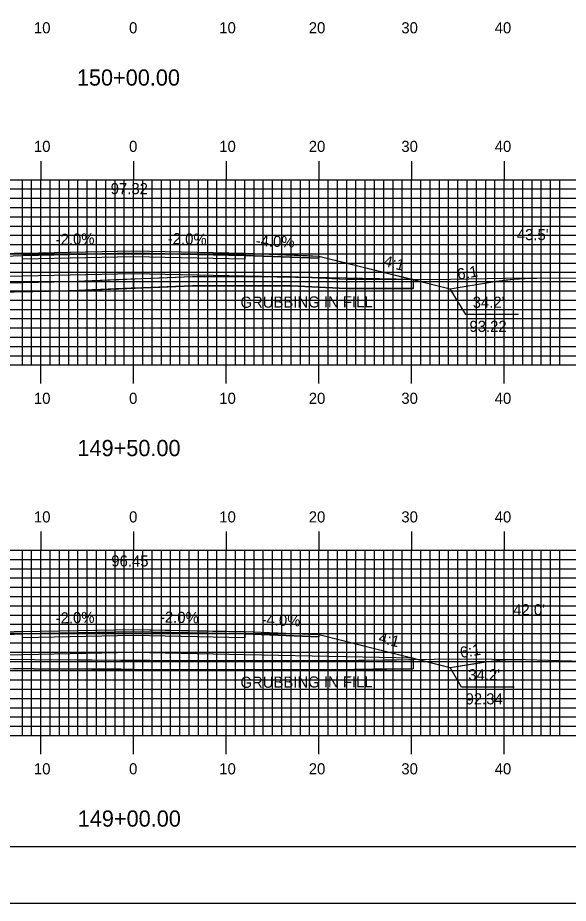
# Model space of a CAD drawing. Extents: x 1778319 to 1778662, y 442591 to 442811.
# Drawn here: x 1778471.8 to 1778531.2, y 442590.5 to 442686.2 of the extents above; entities that cross this region are included whole.
import ezdxf

# ---------------------------------------------------------------- set-up
doc = ezdxf.new("R2010")
doc.units = 0
for name, color, linetype in [('ANNOTATION', 7, 'Continuous'), ('BORDER', 7, 'Continuous'), ('D_Roadway_Centerline', 7, 'Continuous'), ('D_Roadway_Centerline_Text', 7, 'Continuous'), ('D_Roadway_Edge_Shoulder', 7, 'Continuous'), ('D_Roadway_Edge_TW', 7, 'Continuous'), ('D_Roadway_Pavement', 7, 'Continuous'), ('D_Roadway_SlopeLines', 7, 'Continuous'), ('D_Roadway_SubGrade', 7, 'Continuous'), ('D_Text_Standard', 7, 'Continuous'), ('GRUBBING IN FILL', 7, 'Continuous'), ('H_V ANNOTATION', 7, 'Continuous'), ('MAJOR', 7, 'Continuous'), ('MINOR', 7, 'Continuous'), ('PLOT BOUNDARY', 7, 'Continuous'), ('S_Roadway_Centerline', 7, 'Continuous')]:
    doc.layers.add(name, color=color, linetype=linetype)

msp = doc.modelspace()

# ---------------------------------------------------------------- linework, layer by layer
at = {"layer": 'ANNOTATION'}
for points in [[(1778525.862, 442654.108), (1778520.17, 442654.108), (1778518.477, 442656.884)], [(1778525.386, 442613.891), (1778519.694, 442613.891), (1778518.477, 442616.009)]]:
    msp.add_lwpolyline(points, dxfattribs=at)
at = {"layer": 'BORDER'}
msp.add_lwpolyline([(1778334.703, 442596.665), (1778654.703, 442596.665), (1778654.703, 442806.665), (1778334.703, 442806.665)], close=True, dxfattribs=at)
at = {"layer": 'D_Roadway_Centerline'}
for points in [[(1778464.303, 442660.427), (1778472.303, 442660.747), (1778479.279, 442660.887), (1778484.303, 442660.987), (1778496.303, 442660.747), (1778503.045, 442660.478), (1778504.303, 442660.427), (1778514.477, 442657.884), (1778515.433, 442657.645), (1778518.477, 442656.884), (1778522.831, 442657.61), (1778523.447, 442657.7), (1778524.081, 442657.793), (1778524.508, 442657.838), (1778525.331, 442657.925), (1778526.553, 442658.004), (1778526.581, 442658.006), (1778527.831, 442658.036)], [(1778464.303, 442619.552), (1778472.304, 442619.872), (1778484.303, 442620.112), (1778494.598, 442619.906), (1778496.303, 442619.872), (1778504.303, 442619.552), (1778514.476, 442617.009), (1778515.942, 442616.643), (1778518.477, 442616.009), (1778521.317, 442616.482), (1778522.567, 442616.663), (1778523.818, 442616.789), (1778525.068, 442616.859), (1778526.245, 442616.874), (1778526.317, 442616.875)]]:
    msp.add_lwpolyline(points, dxfattribs=at)
at = {"layer": 'D_Roadway_Edge_Shoulder'}
for points in [[(1778472.303, 442660.747), (1778464.303, 442660.427), (1778464.303, 442660.177), (1778472.303, 442660.497)], [(1778496.303, 442660.747), (1778504.303, 442660.427), (1778504.303, 442660.177), (1778496.303, 442660.497)], [(1778472.304, 442619.872), (1778464.303, 442619.552), (1778464.303, 442619.302), (1778472.304, 442619.622)], [(1778496.303, 442619.872), (1778504.303, 442619.552), (1778504.303, 442619.302), (1778496.303, 442619.622)]]:
    msp.add_lwpolyline(points, close=True, dxfattribs=at)
at = {"layer": 'D_Roadway_Edge_TW'}
for points in [[(1778472.303, 442660.497), (1778472.303, 442660.747), (1778484.303, 442660.987), (1778496.303, 442660.747), (1778496.303, 442660.497), (1778484.303, 442660.737)], [(1778472.304, 442619.622), (1778472.304, 442619.872), (1778484.303, 442620.112), (1778496.303, 442619.872), (1778496.303, 442619.622), (1778484.303, 442619.862)]]:
    msp.add_lwpolyline(points, close=True, dxfattribs=at)
at = {"layer": 'D_Roadway_Pavement'}
for points in [[(1778472.303, 442660.081), (1778472.303, 442660.497), (1778484.303, 442660.737), (1778496.303, 442660.497), (1778496.303, 442660.081), (1778484.303, 442660.321)], [(1778472.304, 442619.206), (1778472.304, 442619.622), (1778484.303, 442619.862), (1778496.303, 442619.622), (1778496.303, 442619.206), (1778484.303, 442619.446)]]:
    msp.add_lwpolyline(points, close=True, dxfattribs=at)
at = {"layer": 'D_Roadway_SlopeLines'}
for points in [[(1778504.303, 442660.427), (1778518.477, 442656.884)], [(1778518.477, 442656.884), (1778522.831, 442657.61), (1778524.081, 442657.793), (1778525.331, 442657.925), (1778526.581, 442658.006), (1778527.831, 442658.036)], [(1778504.303, 442619.552), (1778518.477, 442616.009)], [(1778518.477, 442616.009), (1778521.318, 442616.482), (1778522.567, 442616.663), (1778523.818, 442616.789), (1778525.068, 442616.859), (1778526.317, 442616.875)], [(1778518.477, 442616.009), (1778522.567, 442616.663), (1778523.818, 442616.789), (1778525.068, 442616.859), (1778526.317, 442616.875)]]:
    msp.add_lwpolyline(points, dxfattribs=at)
at = {"layer": 'D_Roadway_SubGrade'}
for points in [[(1778472.303, 442658.247), (1778454.129, 442657.884), (1778464.303, 442660.427), (1778464.303, 442660.177), (1778472.303, 442660.497), (1778484.303, 442660.737), (1778496.303, 442660.497), (1778504.303, 442660.177), (1778504.303, 442660.427), (1778514.477, 442657.884), (1778496.303, 442658.247), (1778484.303, 442658.487)], [(1778472.304, 442617.372), (1778454.129, 442617.009), (1778464.303, 442619.552), (1778464.303, 442619.302), (1778472.304, 442619.622), (1778484.303, 442619.862), (1778496.303, 442619.622), (1778504.303, 442619.302), (1778504.303, 442619.552), (1778514.476, 442617.009), (1778496.303, 442617.372), (1778484.303, 442617.612)]]:
    msp.add_lwpolyline(points, close=True, dxfattribs=at)
at = {"layer": 'GRUBBING IN FILL'}
for p, q in [((1778514.477, 442657.884), (1778514.477, 442656.914)), ((1778514.477, 442657.884), (1778514.477, 442656.914)), ((1778514.476, 442617.009), (1778514.476, 442615.871)), ((1778514.476, 442617.009), (1778514.476, 442615.871))]:
    msp.add_line(p, q, dxfattribs=at)
for points in [[(1778454.129, 442657.366), (1778460.678, 442657.418), (1778467.406, 442657.472), (1778472.384, 442657.577), (1778477.362, 442657.682), (1778484.006, 442657.949), (1778484.303, 442657.961), (1778484.303, 442656.961), (1778484.032, 442656.95), (1778477.393, 442656.683), (1778472.407, 442656.577), (1778467.421, 442656.472), (1778460.775, 442656.419), (1778454.129, 442656.366)], [(1778454.129, 442657.366), (1778460.678, 442657.418), (1778467.406, 442657.472), (1778472.384, 442657.577), (1778477.362, 442657.682), (1778484.006, 442657.949), (1778484.303, 442657.961), (1778484.303, 442656.961), (1778484.032, 442656.95), (1778477.393, 442656.683), (1778472.407, 442656.577), (1778467.421, 442656.472), (1778460.775, 442656.419), (1778454.129, 442656.366)], [(1778484.303, 442657.961), (1778490.651, 442658.217), (1778493.523, 442658.218), (1778495.987, 442658.219), (1778497.702, 442658.219), (1778503.82, 442658.097), (1778505.69, 442658.005), (1778507.274, 442657.926), (1778509.862, 442657.917), (1778512.45, 442657.908), (1778513.187, 442657.91), (1778514.477, 442657.884), (1778514.477, 442656.914), (1778513.464, 442656.911), (1778509.849, 442656.917), (1778507.247, 442656.926), (1778501.299, 442657.221), (1778495.985, 442657.219), (1778490.671, 442657.217), (1778484.303, 442656.961)], [(1778484.303, 442657.961), (1778490.651, 442658.217), (1778493.523, 442658.218), (1778495.987, 442658.219), (1778497.702, 442658.219), (1778503.82, 442658.097), (1778505.69, 442658.005), (1778507.274, 442657.926), (1778509.862, 442657.917), (1778512.45, 442657.908), (1778513.187, 442657.91), (1778514.477, 442657.884), (1778514.477, 442656.914), (1778513.464, 442656.911), (1778509.849, 442656.917), (1778507.247, 442656.926), (1778501.299, 442657.221), (1778495.985, 442657.219), (1778490.671, 442657.217), (1778484.303, 442656.961)], [(1778454.129, 442615.647), (1778454.129, 442616.647), (1778459.638, 442616.593), (1778465.061, 442616.725), (1778470.483, 442616.858), (1778472.182, 442616.893), (1778473.6, 442616.865), (1778482.935, 442616.806), (1778484.303, 442616.797), (1778484.303, 442615.797), (1778482.931, 442615.806), (1778473.587, 442615.865), (1778471.344, 442615.876), (1778465.076, 442615.725), (1778459.645, 442615.592), (1778456.887, 442615.62)], [(1778454.129, 442615.647), (1778454.129, 442616.647), (1778459.638, 442616.593), (1778465.061, 442616.725), (1778470.483, 442616.858), (1778472.182, 442616.893), (1778473.6, 442616.865), (1778482.935, 442616.806), (1778484.303, 442616.797), (1778484.303, 442615.797), (1778482.931, 442615.806), (1778473.587, 442615.865), (1778471.344, 442615.876), (1778465.076, 442615.725), (1778459.645, 442615.592), (1778456.887, 442615.62)], [(1778484.303, 442616.797), (1778492.269, 442616.747), (1778495.779, 442616.754), (1778500.838, 442616.751), (1778505.896, 442616.749), (1778512.678, 442616.845), (1778514.476, 442616.871), (1778514.476, 442615.871), (1778510.19, 442615.81), (1778505.903, 442615.749), (1778500.838, 442615.751), (1778494.865, 442615.765), (1778492.274, 442615.747), (1778484.303, 442615.797)], [(1778484.303, 442616.797), (1778492.269, 442616.747), (1778495.779, 442616.754), (1778500.838, 442616.751), (1778505.896, 442616.749), (1778512.678, 442616.845), (1778514.476, 442616.871), (1778514.476, 442615.871), (1778510.19, 442615.81), (1778505.903, 442615.749), (1778500.838, 442615.751), (1778494.865, 442615.765), (1778492.274, 442615.747), (1778484.303, 442615.797)]]:
    msp.add_lwpolyline(points, close=True, dxfattribs=at)
for points in [[(1778454.129, 442656.366), (1778467.421, 442656.472), (1778477.393, 442656.683), (1778490.671, 442657.217), (1778501.299, 442657.221), (1778507.247, 442656.926), (1778512.45, 442656.908), (1778514.477, 442656.914)], [(1778454.129, 442656.366), (1778467.421, 442656.472), (1778477.393, 442656.683), (1778490.671, 442657.217), (1778501.299, 442657.221), (1778507.247, 442656.926), (1778512.45, 442656.908), (1778514.477, 442656.914)], [(1778454.129, 442615.647), (1778459.645, 442615.592), (1778470.506, 442615.858), (1778472.182, 442615.893), (1778473.587, 442615.865), (1778492.274, 442615.747), (1778493.957, 442615.775), (1778495.773, 442615.754), (1778505.903, 442615.749), (1778514.476, 442615.871)], [(1778454.129, 442615.647), (1778459.645, 442615.592), (1778470.506, 442615.858), (1778472.182, 442615.893), (1778473.587, 442615.865), (1778492.274, 442615.747), (1778493.957, 442615.775), (1778495.773, 442615.754), (1778505.903, 442615.749), (1778514.476, 442615.871)]]:
    msp.add_lwpolyline(points, dxfattribs=at)
at = {"layer": 'MAJOR'}
for p, q in [((1778474.303, 442670.669), (1778474.303, 442668.665)), ((1778484.303, 442670.669), (1778484.303, 442668.665)), ((1778494.303, 442670.669), (1778494.303, 442668.665)), ((1778504.303, 442670.669), (1778504.303, 442668.665)), ((1778514.303, 442670.669), (1778514.303, 442668.665)), ((1778524.303, 442670.669), (1778524.303, 442668.665)), ((1778344.303, 442668.665), (1778624.303, 442668.665)), ((1778344.303, 442668.665), (1778624.303, 442668.665)), ((1778474.303, 442648.665), (1778474.303, 442668.665)), ((1778484.303, 442648.665), (1778484.303, 442668.665)), ((1778494.303, 442648.665), (1778494.303, 442668.665)), ((1778504.303, 442648.665), (1778504.303, 442668.665)), ((1778514.303, 442648.665), (1778514.303, 442668.665)), ((1778524.303, 442648.665), (1778524.303, 442668.665)), ((1778344.303, 442663.665), (1778624.303, 442663.665)), ((1778344.303, 442658.665), (1778624.303, 442658.665)), ((1778344.303, 442653.665), (1778624.303, 442653.665)), ((1778344.303, 442648.665), (1778624.303, 442648.665)), ((1778344.303, 442648.665), (1778624.303, 442648.665)), ((1778474.303, 442646.661), (1778474.303, 442648.665)), ((1778484.303, 442646.661), (1778484.303, 442648.665)), ((1778494.303, 442646.661), (1778494.303, 442648.665)), ((1778504.303, 442646.661), (1778504.303, 442648.665)), ((1778514.303, 442646.661), (1778514.303, 442648.665)), ((1778524.303, 442646.661), (1778524.303, 442648.665)), ((1778474.303, 442630.669), (1778474.303, 442628.665)), ((1778484.303, 442630.669), (1778484.303, 442628.665)), ((1778494.303, 442630.669), (1778494.303, 442628.665)), ((1778504.303, 442630.669), (1778504.303, 442628.665)), ((1778514.303, 442630.669), (1778514.303, 442628.665)), ((1778524.303, 442630.669), (1778524.303, 442628.665)), ((1778344.303, 442628.665), (1778624.303, 442628.665)), ((1778344.303, 442628.665), (1778624.303, 442628.665)), ((1778474.303, 442608.665), (1778474.303, 442628.665)), ((1778484.303, 442608.665), (1778484.303, 442628.665)), ((1778494.303, 442608.665), (1778494.303, 442628.665)), ((1778504.303, 442608.665), (1778504.303, 442628.665)), ((1778514.303, 442608.665), (1778514.303, 442628.665)), ((1778524.303, 442608.665), (1778524.303, 442628.665)), ((1778344.303, 442623.665), (1778624.303, 442623.665)), ((1778344.303, 442618.665), (1778624.303, 442618.665)), ((1778344.303, 442613.665), (1778624.303, 442613.665)), ((1778344.303, 442608.665), (1778624.303, 442608.665)), ((1778344.303, 442608.665), (1778624.303, 442608.665)), ((1778474.303, 442606.661), (1778474.303, 442608.665)), ((1778484.303, 442606.661), (1778484.303, 442608.665)), ((1778494.303, 442606.661), (1778494.303, 442608.665)), ((1778504.303, 442606.661), (1778504.303, 442608.665)), ((1778514.303, 442606.661), (1778514.303, 442608.665)), ((1778524.303, 442606.661), (1778524.303, 442608.665))]:
    msp.add_line(p, q, dxfattribs=at)
at = {"layer": 'MINOR'}
for p, q in [((1778472.303, 442648.665), (1778472.303, 442668.665)), ((1778473.303, 442648.665), (1778473.303, 442668.665)), ((1778475.303, 442648.665), (1778475.303, 442668.665)), ((1778476.303, 442648.665), (1778476.303, 442668.665)), ((1778477.303, 442648.665), (1778477.303, 442668.665)), ((1778478.303, 442648.665), (1778478.303, 442668.665)), ((1778479.303, 442648.665), (1778479.303, 442668.665)), ((1778480.303, 442648.665), (1778480.303, 442668.665)), ((1778481.303, 442648.665), (1778481.303, 442668.665)), ((1778482.303, 442648.665), (1778482.303, 442668.665)), ((1778483.303, 442648.665), (1778483.303, 442668.665)), ((1778485.303, 442648.665), (1778485.303, 442668.665)), ((1778486.303, 442648.665), (1778486.303, 442668.665)), ((1778487.303, 442648.665), (1778487.303, 442668.665)), ((1778488.303, 442648.665), (1778488.303, 442668.665)), ((1778489.303, 442648.665), (1778489.303, 442668.665)), ((1778490.303, 442648.665), (1778490.303, 442668.665)), ((1778491.303, 442648.665), (1778491.303, 442668.665)), ((1778492.303, 442648.665), (1778492.303, 442668.665)), ((1778493.303, 442648.665), (1778493.303, 442668.665)), ((1778495.303, 442648.665), (1778495.303, 442668.665)), ((1778496.303, 442648.665), (1778496.303, 442668.665)), ((1778497.303, 442648.665), (1778497.303, 442668.665)), ((1778498.303, 442648.665), (1778498.303, 442668.665)), ((1778499.303, 442648.665), (1778499.303, 442668.665)), ((1778500.303, 442648.665), (1778500.303, 442668.665)), ((1778501.303, 442648.665), (1778501.303, 442668.665)), ((1778502.303, 442648.665), (1778502.303, 442668.665)), ((1778503.303, 442648.665), (1778503.303, 442668.665)), ((1778505.303, 442648.665), (1778505.303, 442668.665)), ((1778506.303, 442648.665), (1778506.303, 442668.665)), ((1778507.303, 442648.665), (1778507.303, 442668.665)), ((1778508.303, 442648.665), (1778508.303, 442668.665)), ((1778509.303, 442648.665), (1778509.303, 442668.665)), ((1778510.303, 442648.665), (1778510.303, 442668.665)), ((1778511.303, 442648.665), (1778511.303, 442668.665)), ((1778512.303, 442648.665), (1778512.303, 442668.665)), ((1778513.303, 442648.665), (1778513.303, 442668.665)), ((1778515.303, 442648.665), (1778515.303, 442668.665)), ((1778516.303, 442648.665), (1778516.303, 442668.665)), ((1778517.303, 442648.665), (1778517.303, 442668.665)), ((1778518.303, 442648.665), (1778518.303, 442668.665)), ((1778519.303, 442648.665), (1778519.303, 442668.665)), ((1778520.303, 442648.665), (1778520.303, 442668.665)), ((1778521.303, 442648.665), (1778521.303, 442668.665)), ((1778522.303, 442648.665), (1778522.303, 442668.665)), ((1778523.303, 442648.665), (1778523.303, 442668.665)), ((1778525.303, 442648.665), (1778525.303, 442668.665)), ((1778526.303, 442648.665), (1778526.303, 442668.665)), ((1778527.303, 442648.665), (1778527.303, 442668.665)), ((1778528.303, 442648.665), (1778528.303, 442668.665)), ((1778529.303, 442648.665), (1778529.303, 442668.665)), ((1778530.303, 442648.665), (1778530.303, 442668.665)), ((1778344.303, 442667.665), (1778624.303, 442667.665)), ((1778344.303, 442666.665), (1778624.303, 442666.665)), ((1778344.303, 442665.665), (1778624.303, 442665.665)), ((1778344.303, 442664.665), (1778624.303, 442664.665)), ((1778344.303, 442662.665), (1778624.303, 442662.665)), ((1778344.303, 442661.665), (1778624.303, 442661.665)), ((1778344.303, 442660.665), (1778624.303, 442660.665)), ((1778344.303, 442659.665), (1778624.303, 442659.665)), ((1778344.303, 442657.665), (1778624.303, 442657.665)), ((1778344.303, 442656.665), (1778624.303, 442656.665)), ((1778344.303, 442655.665), (1778624.303, 442655.665)), ((1778344.303, 442654.665), (1778624.303, 442654.665)), ((1778344.303, 442652.665), (1778624.303, 442652.665)), ((1778344.303, 442651.665), (1778624.303, 442651.665)), ((1778344.303, 442650.665), (1778624.303, 442650.665)), ((1778344.303, 442649.665), (1778624.303, 442649.665)), ((1778472.303, 442608.665), (1778472.303, 442628.665)), ((1778473.303, 442608.665), (1778473.303, 442628.665)), ((1778475.303, 442608.665), (1778475.303, 442628.665)), ((1778476.303, 442608.665), (1778476.303, 442628.665)), ((1778477.303, 442608.665), (1778477.303, 442628.665)), ((1778478.303, 442608.665), (1778478.303, 442628.665)), ((1778479.303, 442608.665), (1778479.303, 442628.665)), ((1778480.303, 442608.665), (1778480.303, 442628.665)), ((1778481.303, 442608.665), (1778481.303, 442628.665)), ((1778482.303, 442608.665), (1778482.303, 442628.665)), ((1778483.303, 442608.665), (1778483.303, 442628.665)), ((1778485.303, 442608.665), (1778485.303, 442628.665)), ((1778486.303, 442608.665), (1778486.303, 442628.665)), ((1778487.303, 442608.665), (1778487.303, 442628.665)), ((1778488.303, 442608.665), (1778488.303, 442628.665)), ((1778489.303, 442608.665), (1778489.303, 442628.665)), ((1778490.303, 442608.665), (1778490.303, 442628.665)), ((1778491.303, 442608.665), (1778491.303, 442628.665)), ((1778492.303, 442608.665), (1778492.303, 442628.665)), ((1778493.303, 442608.665), (1778493.303, 442628.665)), ((1778495.303, 442608.665), (1778495.303, 442628.665)), ((1778496.303, 442608.665), (1778496.303, 442628.665)), ((1778497.303, 442608.665), (1778497.303, 442628.665)), ((1778498.303, 442608.665), (1778498.303, 442628.665)), ((1778499.303, 442608.665), (1778499.303, 442628.665)), ((1778500.303, 442608.665), (1778500.303, 442628.665)), ((1778501.303, 442608.665), (1778501.303, 442628.665)), ((1778502.303, 442608.665), (1778502.303, 442628.665)), ((1778503.303, 442608.665), (1778503.303, 442628.665)), ((1778505.303, 442608.665), (1778505.303, 442628.665)), ((1778506.303, 442608.665), (1778506.303, 442628.665)), ((1778507.303, 442608.665), (1778507.303, 442628.665)), ((1778508.303, 442608.665), (1778508.303, 442628.665)), ((1778509.303, 442608.665), (1778509.303, 442628.665)), ((1778510.303, 442608.665), (1778510.303, 442628.665)), ((1778511.303, 442608.665), (1778511.303, 442628.665)), ((1778512.303, 442608.665), (1778512.303, 442628.665)), ((1778513.303, 442608.665), (1778513.303, 442628.665)), ((1778515.303, 442608.665), (1778515.303, 442628.665)), ((1778516.303, 442608.665), (1778516.303, 442628.665)), ((1778517.303, 442608.665), (1778517.303, 442628.665)), ((1778518.303, 442608.665), (1778518.303, 442628.665)), ((1778519.303, 442608.665), (1778519.303, 442628.665)), ((1778520.303, 442608.665), (1778520.303, 442628.665)), ((1778521.303, 442608.665), (1778521.303, 442628.665)), ((1778522.303, 442608.665), (1778522.303, 442628.665)), ((1778523.303, 442608.665), (1778523.303, 442628.665)), ((1778525.303, 442608.665), (1778525.303, 442628.665)), ((1778526.303, 442608.665), (1778526.303, 442628.665)), ((1778527.303, 442608.665), (1778527.303, 442628.665)), ((1778528.303, 442608.665), (1778528.303, 442628.665)), ((1778529.303, 442608.665), (1778529.303, 442628.665)), ((1778530.303, 442608.665), (1778530.303, 442628.665)), ((1778344.303, 442627.665), (1778624.303, 442627.665)), ((1778344.303, 442626.665), (1778624.303, 442626.665)), ((1778344.303, 442625.665), (1778624.303, 442625.665)), ((1778344.303, 442624.665), (1778624.303, 442624.665)), ((1778344.303, 442622.665), (1778624.303, 442622.665)), ((1778344.303, 442621.665), (1778624.303, 442621.665)), ((1778344.303, 442620.665), (1778624.303, 442620.665)), ((1778344.303, 442619.665), (1778624.303, 442619.665)), ((1778344.303, 442617.665), (1778624.303, 442617.665)), ((1778344.303, 442616.665), (1778624.303, 442616.665)), ((1778344.303, 442615.665), (1778624.303, 442615.665)), ((1778344.303, 442614.665), (1778624.303, 442614.665)), ((1778344.303, 442612.665), (1778624.303, 442612.665)), ((1778344.303, 442611.665), (1778624.303, 442611.665)), ((1778344.303, 442610.665), (1778624.303, 442610.665)), ((1778344.303, 442609.665), (1778624.303, 442609.665))]:
    msp.add_line(p, q, dxfattribs=at)
at = {"layer": 'PLOT BOUNDARY'}
msp.add_lwpolyline([(1778318.516, 442590.547), (1778658.516, 442590.547), (1778658.516, 442810.547), (1778318.516, 442810.547)], close=True, dxfattribs=at)
at = {"layer": 'S_Roadway_Centerline'}
for points in [[(1778344.303, 442656.471), (1778344.405, 442656.479), (1778353.961, 442656.277), (1778358.625, 442656.431), (1778376.722, 442656.73), (1778379.183, 442656.575), (1778398.717, 442657.351), (1778401.625, 442657.468), (1778421.743, 442657.422), (1778424.302, 442657.366), (1778429.2, 442657.402), (1778437.29, 442657.57), (1778444.876, 442657.439), (1778449.457, 442657.46), (1778453.95, 442657.364), (1778467.406, 442657.472), (1778477.362, 442657.682), (1778490.651, 442658.217), (1778501.324, 442658.221), (1778507.274, 442657.926), (1778512.45, 442657.908), (1778518.537, 442657.927), (1778524.414, 442658.023), (1778539.78, 442658.085)], [(1778402.176, 442616.154), (1778425.622, 442616.168), (1778426.457, 442616.2), (1778436.939, 442616.743), (1778447.845, 442616.709), (1778459.638, 442616.593), (1778470.483, 442616.858), (1778472.182, 442616.893), (1778473.6, 442616.865), (1778492.269, 442616.747), (1778493.954, 442616.775), (1778495.779, 442616.754), (1778505.896, 442616.749), (1778519.459, 442616.942), (1778526.587, 442616.872), (1778539.023, 442616.524)]]:
    msp.add_lwpolyline(points, dxfattribs=at)

# ---------------------------------------------------------------- texts
at = {"layer": 'ANNOTATION'}
for s, rotation, p in [('-2.0%', 1.14576, (1778475.909, 442661.62)), ('-2.0%', 358.85424, (1778487.989, 442661.714)), ('-4.0%', 357.70926, (1778497.466, 442661.502)), ('4:1', 345.9671, (1778511.215, 442659.352)), ('6:1', 9.46629, (1778519.329, 442657.854)), ('-2.0%', 1.14582, (1778475.909, 442620.745)), ('-2.0%', 358.85424, (1778487.137, 442620.856)), ('-4.0%', 357.70947, (1778498.095, 442620.602)), ('4:1', 345.96523, (1778510.661, 442618.716)), ('6:1', 9.45408, (1778519.635, 442617.022))]:
    msp.add_text(s, height=1.2, rotation=rotation, dxfattribs=at).set_placement(p)
for s, p in [("34.2'", (1778520.905, 442654.834)), ('93.22', (1778520.551, 442652.234)), ("34.2'", (1778520.429, 442614.617)), ('92.34', (1778520.134, 442612.017))]:
    msp.add_text(s, height=1.2, dxfattribs=at).set_placement(p)
at = {"layer": 'D_Roadway_Centerline'}
for s, p in [('C', (1778484.298, 442660.987)), ('L', (1778484.303, 442660.98)), ('C', (1778484.298, 442620.112)), ('L', (1778484.303, 442620.105))]:
    msp.add_text(s, height=0.0146, dxfattribs=at).set_placement(p)
at = {"layer": 'D_Roadway_Centerline_Text'}
for s, p in [('97.32', (1778481.836, 442667.1)), ('96.45', (1778481.901, 442626.906))]:
    msp.add_text(s, height=1.2, dxfattribs=at).set_placement(p)
at = {"layer": 'D_Text_Standard'}
for s, p in [("43.5'", (1778525.664, 442662.136)), ("42.0'", (1778525.275, 442621.639))]:
    msp.add_text(s, height=1.2, dxfattribs=at).set_placement(p)
at = {"layer": 'GRUBBING IN FILL'}
for p in [(1778495.84, 442654.833), (1778495.84, 442613.805)]:
    msp.add_text('GRUBBING IN FILL', height=1.2, rotation=0.24521, dxfattribs=at).set_placement(p)
at = {"layer": 'H_V ANNOTATION'}
for s, height, p in [('10', 1.2, (1778473.554, 442684.465)), ('0', 1.2, (1778483.821, 442684.465)), ('10', 1.2, (1778493.554, 442684.465)), ('20', 1.2, (1778503.211, 442684.465)), ('30', 1.2, (1778513.2, 442684.465)), ('40', 1.2, (1778523.275, 442684.465)), ('150+00.00', 1.75, (1778478.185, 442678.821)), ('10', 1.2, (1778473.554, 442671.665)), ('0', 1.2, (1778483.821, 442671.665)), ('10', 1.2, (1778493.554, 442671.665)), ('20', 1.2, (1778503.211, 442671.665)), ('30', 1.2, (1778513.2, 442671.665)), ('40', 1.2, (1778523.275, 442671.665)), ('10', 1.2, (1778473.554, 442644.465)), ('0', 1.2, (1778483.821, 442644.465)), ('10', 1.2, (1778493.554, 442644.465)), ('20', 1.2, (1778503.211, 442644.465)), ('30', 1.2, (1778513.2, 442644.465)), ('40', 1.2, (1778523.275, 442644.465)), ('149+50.00', 1.75, (1778478.248, 442638.821)), ('10', 1.2, (1778473.554, 442631.665)), ('0', 1.2, (1778483.821, 442631.665)), ('10', 1.2, (1778493.554, 442631.665)), ('20', 1.2, (1778503.211, 442631.665)), ('30', 1.2, (1778513.2, 442631.665)), ('40', 1.2, (1778523.275, 442631.665)), ('10', 1.2, (1778473.554, 442604.465)), ('0', 1.2, (1778483.821, 442604.465)), ('10', 1.2, (1778493.554, 442604.465)), ('20', 1.2, (1778503.211, 442604.465)), ('30', 1.2, (1778513.2, 442604.465)), ('40', 1.2, (1778523.275, 442604.465)), ('149+00.00', 1.75, (1778478.279, 442598.821))]:
    msp.add_text(s, height=height, dxfattribs=at).set_placement(p)

doc.saveas('drawing.dxf')
